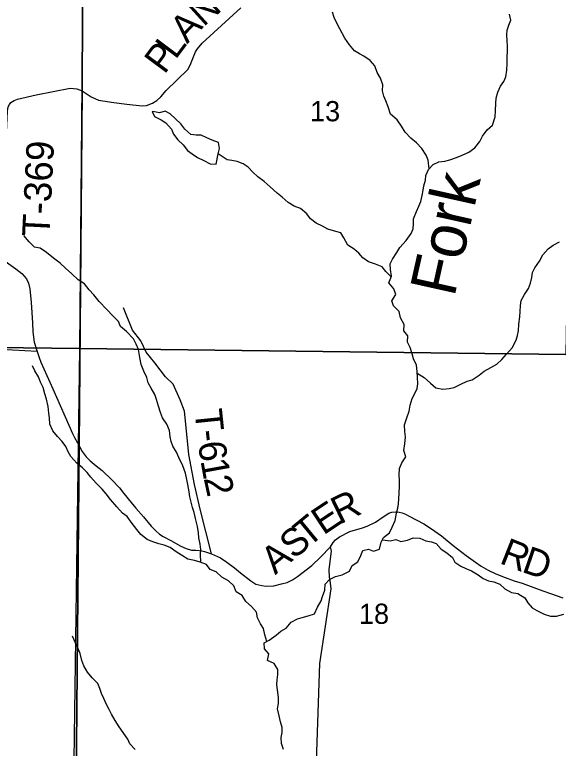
# Model space of a CAD drawing. Extents: x -3.6 to 34, y 0 to 32.8.
# Drawn here: x -2.947 to -1.822, y 28.286 to 29.806 of the extents above; entities that cross this region are included whole.
import ezdxf

# ---------------------------------------------------------------- set-up
doc = ezdxf.new("R2010")
doc.units = 0
for name, color, linetype in [('GM_X_Corporation', 7, 'Continuous'), ('GM_X_County_Road', 7, 'Continuous'), ('GM_X_County_Road_Text', 7, 'Continuous'), ('GM_X_Minor_Lake', 7, 'Continuous'), ('GM_X_Minor_River', 7, 'Continuous'), ('GM_X_Minor_River_Text', 7, 'Continuous'), ('GM_X_Section_Text', 7, 'Continuous'), ('GM_X_Township_Road', 7, 'Continuous'), ('GM_X_Township_Road_Text', 7, 'Continuous')]:
    doc.layers.add(name, color=color, linetype=linetype)

msp = doc.modelspace()

# ---------------------------------------------------------------- linework, layer by layer
at = {"layer": 'GM_X_Corporation'}
for points in [[(-3.6295, 30.6462), (-3.6295, 26.0429), (-2.8635, 26.0429), (-2.8499, 26.4099), (-2.8426, 27.1), (-2.8208, 28.0589), (-2.813, 28.9119), (-2.8073, 29.6484), (-2.8047, 30.129), (-2.8012, 30.524), (-2.8007, 30.6338), (-3.5736, 30.6453)], [(-3.6295, 30.1386), (-3.6295, 29.124), (-2.8121, 29.1143), (-2.8032, 30.1329)], [(-1.7886, 30.1145), (-1.8059, 29.1018), (-2.8121, 29.1143), (-2.8032, 30.1329)], [(-3.6295, 29.124), (-3.6295, 28.0641), (-2.8264, 28.0607), (-2.8121, 29.1143)], [(-2.8121, 29.1143), (-1.8059, 29.1018), (-1.7854, 29.1006), (-1.8056, 28.0368), (-2.8264, 28.0607)]]:
    msp.add_lwpolyline(points, close=True, dxfattribs=at)
msp.add_lwpolyline([(-0.398, 30.5946), (-0.453, 30.5952), (-0.5034, 30.5954), (-2.3541, 30.6318), (-2.7027, 30.634), (-2.8007, 30.6338), (-2.8012, 30.524), (-2.8047, 30.129), (-2.8073, 29.6484), (-2.813, 28.9119), (-2.8208, 28.0589), (-2.8426, 27.1), (-2.8499, 26.4099), (-2.8635, 26.0429), (2.3706, 26.0429)], dxfattribs=at)
at = {"layer": 'GM_X_County_Road'}
for points in [[(-2.976, 29.3021), (-2.9446, 29.2795), (-2.9318, 29.2695), (-2.922, 29.2586), (-2.9182, 29.2497), (-2.9154, 29.2377), (-2.9127, 29.2098), (-2.91, 29.1674), (-2.9089, 29.1491), (-2.9061, 29.1277), (-2.9005, 29.1079), (-2.8964, 29.0957), (-2.8926, 29.0857), (-2.8677, 29.0305), (-2.8274, 28.9384), (-2.8228, 28.9298), (-2.8167, 28.9188), (-2.8162, 28.9179)], [(-2.8162, 28.9179), (-2.8128, 28.9113), (-2.8074, 28.9009), (-2.7989, 28.89), (-2.7904, 28.8818), (-2.7778, 28.8715), (-2.7654, 28.8617), (-2.7449, 28.8417), (-2.7301, 28.8256), (-2.7206, 28.814), (-2.7055, 28.7956), (-2.696, 28.7836), (-2.6803, 28.7656), (-2.6642, 28.7461), (-2.6545, 28.7369), (-2.6468, 28.7296), (-2.6392, 28.7252), (-2.6239, 28.7165), (-2.6032, 28.7052), (-2.5915, 28.7), (-2.5806, 28.6969), (-2.5721, 28.6964), (-2.5652, 28.6961), (-2.5593, 28.6953), (-2.5542, 28.6938), (-2.5391, 28.6891), (-2.5209, 28.6811), (-2.508, 28.6715), (-2.4916, 28.6604), (-2.4797, 28.65), (-2.458, 28.6332), (-2.4476, 28.6265), (-2.4351, 28.6232), (-2.4266, 28.622), (-2.4107, 28.6231), (-2.3948, 28.6267), (-2.3827, 28.6299), (-2.3716, 28.6353), (-2.3617, 28.6424), (-2.332, 28.665), (-2.314, 28.682), (-2.293, 28.7034), (-2.2875, 28.7126), (-2.283, 28.7182), (-2.2744, 28.7246), (-2.2533, 28.7352), (-2.2268, 28.7428), (-2.217, 28.7465), (-2.2003, 28.7547), (-2.1841, 28.7655), (-2.1721, 28.7731), (-2.1662, 28.7752), (-2.1596, 28.776), (-2.1511, 28.7756), (-2.1448, 28.7737), (-2.138, 28.7709), (-2.1304, 28.7672), (-2.1, 28.7513), (-2.0843, 28.7409), (-2.0636, 28.7264), (-2.0393, 28.7061), (-2.012, 28.6856), (-1.9932, 28.6719), (-1.981, 28.6637), (-1.9666, 28.655), (-1.9507, 28.6473), (-1.9316, 28.64), (-1.9127, 28.6333), (-1.8963, 28.6281), (-1.8538, 28.6122), (-1.8378, 28.6067), (-1.8123, 28.5976)]]:
    msp.add_lwpolyline(points, dxfattribs=at)
at = {"layer": 'GM_X_Minor_Lake'}
for points in [[(-2.6576, 29.6045), (-2.6625, 29.6055), (-2.6574, 29.595), (-2.6437, 29.588), (-2.6337, 29.5817), (-2.6225, 29.5687), (-2.6182, 29.5585), (-2.6092, 29.5462), (-2.5981, 29.5361), (-2.5888, 29.5241), (-2.5792, 29.5175), (-2.5681, 29.5101), (-2.5551, 29.5035), (-2.5425, 29.4969), (-2.5296, 29.496), (-2.5259, 29.5173)], [(-2.5259, 29.5173), (-2.523, 29.5283), (-2.5247, 29.5412), (-2.5377, 29.5455), (-2.5491, 29.5506), (-2.5606, 29.5561), (-2.5708, 29.5563), (-2.5822, 29.5576), (-2.5949, 29.5688), (-2.603, 29.5796), (-2.6138, 29.59), (-2.625, 29.6005), (-2.6356, 29.606), (-2.6473, 29.6024), (-2.6576, 29.6045)]]:
    msp.add_lwpolyline(points, dxfattribs=at)
at = {"layer": 'GM_X_Minor_River'}
for points in [[(-2.0887, 29.4867), (-2.0911, 29.5042), (-2.0954, 29.5148), (-2.104, 29.5283), (-2.1148, 29.5406), (-2.1267, 29.5502), (-2.1386, 29.5625), (-2.1464, 29.5749), (-2.1554, 29.588), (-2.1688, 29.5999), (-2.1736, 29.6146), (-2.1787, 29.6274), (-2.1827, 29.6372), (-2.1855, 29.6478), (-2.185, 29.6607), (-2.1894, 29.6742), (-2.1968, 29.6859), (-2.2016, 29.6998), (-2.2112, 29.7106), (-2.2239, 29.7195), (-2.2334, 29.7247), (-2.2434, 29.7309), (-2.2538, 29.7429), (-2.2631, 29.7571), (-2.2741, 29.7767), (-2.2799, 29.7883), (-2.2854, 29.7996), (-2.2887, 29.8109)], [(-2.2306, 28.6857), (-2.2263, 28.6957), (-2.2146, 28.6985), (-2.2043, 28.6945), (-2.1915, 28.6989), (-2.1883, 28.7134), (-2.1832, 28.7229), (-2.1713, 28.7326), (-2.1654, 28.7441), (-2.1596, 28.7578), (-2.1564, 28.7731), (-2.154, 28.7833), (-2.1526, 28.7928), (-2.152, 28.8031), (-2.1507, 28.8149), (-2.1502, 28.8289), (-2.1504, 28.841), (-2.151, 28.8524), (-2.1505, 28.8657), (-2.1454, 28.8775), (-2.1373, 28.8901), (-2.1416, 28.903), (-2.1396, 28.9166), (-2.138, 28.9311), (-2.1393, 28.9424), (-2.1399, 28.9561), (-2.1349, 28.9705), (-2.1306, 28.9843), (-2.1285, 28.9972), (-2.1238, 29.0105), (-2.1183, 29.0212), (-2.1136, 29.0316), (-2.1122, 29.0414), (-2.1132, 29.0551), (-2.1134, 29.0668), (-2.1148, 29.0797), (-2.1215, 29.0932), (-2.1239, 29.1034), (-2.1283, 29.1166), (-2.1334, 29.1275), (-2.1333, 29.1408), (-2.141, 29.1509), (-2.1405, 29.1641), (-2.1483, 29.178), (-2.1512, 29.1912), (-2.1627, 29.2028), (-2.1663, 29.213), (-2.1578, 29.226), (-2.1622, 29.2381), (-2.1726, 29.2504), (-2.1672, 29.2641), (-2.1689, 29.2777), (-2.1695, 29.2899), (-2.1651, 29.2994), (-2.1555, 29.3128), (-2.1493, 29.3236), (-2.1366, 29.3378), (-2.1259, 29.3528), (-2.1219, 29.3623), (-2.1214, 29.3726), (-2.1215, 29.3832), (-2.1154, 29.3984), (-2.1102, 29.4091), (-2.1059, 29.4187), (-2.1034, 29.4309), (-2.101, 29.4419), (-2.0996, 29.4514), (-2.0968, 29.4628), (-2.0958, 29.4727), (-2.09, 29.4853), (-2.0807, 29.4953), (-2.0687, 29.5008), (-2.0566, 29.5025), (-2.0464, 29.5054), (-2.0325, 29.5098), (-2.0208, 29.5145), (-2.0069, 29.5208), (-1.9942, 29.5301), (-1.9842, 29.5428), (-1.9787, 29.5539), (-1.9691, 29.567), (-1.9576, 29.5766), (-1.9526, 29.5941), (-1.9516, 29.6063), (-1.9512, 29.6222), (-1.9502, 29.6325), (-1.947, 29.6454), (-1.9415, 29.6576), (-1.9345, 29.6672), (-1.9301, 29.6768), (-1.9281, 29.6908), (-1.9272, 29.7045), (-1.9274, 29.7174), (-1.9269, 29.731), (-1.9271, 29.7409), (-1.9276, 29.7507), (-1.9279, 29.764), (-1.9276, 29.7735), (-1.924, 29.7842), (-1.9201, 29.7941), (-1.9225, 29.8069)], [(-2.1677, 29.2628), (-2.1787, 29.2738), (-2.1861, 29.2835), (-2.1998, 29.2893), (-2.2142, 29.2936), (-2.2261, 29.3018), (-2.2342, 29.3115), (-2.2442, 29.32), (-2.2572, 29.3282), (-2.2654, 29.3432), (-2.2717, 29.3537), (-2.282, 29.3565), (-2.2983, 29.3612), (-2.3098, 29.3674), (-2.3231, 29.374), (-2.3346, 29.3829), (-2.3424, 29.3934), (-2.3551, 29.4046), (-2.3684, 29.4089), (-2.3806, 29.4166), (-2.3933, 29.4274), (-2.4033, 29.4363), (-2.4183, 29.449), (-2.4306, 29.4605), (-2.4433, 29.4702), (-2.454, 29.4794), (-2.4637, 29.4899), (-2.4736, 29.4965), (-2.4862, 29.5016), (-2.4976, 29.5037), (-2.5071, 29.5054), (-2.5259, 29.5173)], [(-2.5618, 28.6714), (-2.5619, 28.6884), (-2.5617, 28.6979), (-2.5627, 28.7093), (-2.5655, 28.7221), (-2.5665, 28.7323), (-2.5686, 28.7459), (-2.5726, 28.7622), (-2.5751, 28.7746), (-2.5787, 28.7852), (-2.5812, 28.7961), (-2.584, 28.8074), (-2.5857, 28.8176), (-2.5882, 28.8328), (-2.5907, 28.8433), (-2.5932, 28.8562), (-2.5984, 28.8716), (-2.607, 28.8889), (-2.6117, 28.8995), (-2.6195, 28.9118), (-2.6227, 28.9216), (-2.6248, 28.9315), (-2.6265, 28.9443), (-2.632, 28.9575), (-2.6406, 28.9706), (-2.6453, 28.9815), (-2.649, 28.9951), (-2.6534, 29.0087), (-2.6569, 29.0188), (-2.6644, 29.0324), (-2.6702, 29.0433), (-2.6734, 29.0542), (-2.6794, 29.0674), (-2.6853, 29.0809), (-2.6874, 29.096), (-2.6903, 29.1123), (-2.6951, 29.1232), (-2.7009, 29.1341), (-2.7152, 29.1494), (-2.7275, 29.1598), (-2.7318, 29.1699), (-2.7434, 29.1819), (-2.7558, 29.1953), (-2.7716, 29.2117), (-2.7828, 29.2252), (-2.7924, 29.236), (-2.8025, 29.248), (-2.8151, 29.2568), (-2.8282, 29.2691), (-2.8416, 29.281), (-2.8528, 29.2911), (-2.8662, 29.3015), (-2.8812, 29.313), (-2.8942, 29.3218), (-2.906, 29.3239), (-2.9168, 29.3351), (-2.928, 29.3485)], [(-2.1134, 29.063), (-2.0992, 29.0542), (-2.0861, 29.0423), (-2.075, 29.0326), (-2.0606, 29.0298), (-2.0473, 29.0312), (-2.0372, 29.0336), (-2.0233, 29.0403), (-2.0101, 29.0466), (-1.9996, 29.0494), (-1.9854, 29.0591), (-1.9749, 29.0677), (-1.9614, 29.0747), (-1.949, 29.0818), (-1.9382, 29.0914), (-1.9286, 29.1026), (-1.9171, 29.116), (-1.909, 29.1313), (-1.9058, 29.1409), (-1.9037, 29.1508), (-1.9035, 29.1648), (-1.9015, 29.1796), (-1.9006, 29.191), (-1.9, 29.2031), (-1.8987, 29.2134), (-1.8913, 29.226), (-1.8836, 29.2387), (-1.8789, 29.2497), (-1.8764, 29.2611), (-1.8747, 29.2714), (-1.8703, 29.2817), (-1.8607, 29.2951), (-1.8534, 29.3085), (-1.8426, 29.3205), (-1.8322, 29.3286), (-1.8194, 29.3353)], [(-2.4247, 28.5077), (-2.4292, 28.5212), (-2.4321, 28.5341), (-2.4379, 28.5442), (-2.4442, 28.5566), (-2.4463, 28.568), (-2.4567, 28.5803), (-2.4686, 28.5903), (-2.4757, 28.6027), (-2.4883, 28.6105), (-2.493, 28.6225), (-2.5042, 28.6333), (-2.5179, 28.6406), (-2.5295, 28.6518), (-2.5421, 28.6565), (-2.5498, 28.667), (-2.5628, 28.6717), (-2.5746, 28.6753), (-2.5886, 28.6781), (-2.6016, 28.6866), (-2.6123, 28.6932), (-2.625, 28.7021), (-2.6372, 28.7068), (-2.6486, 28.7101), (-2.6608, 28.714), (-2.6726, 28.7187), (-2.6856, 28.7291), (-2.6938, 28.7392), (-2.7035, 28.752), (-2.7139, 28.7662), (-2.7235, 28.7736), (-2.7351, 28.7863), (-2.7486, 28.8016), (-2.7571, 28.8132), (-2.766, 28.8229), (-2.7783, 28.8356), (-2.7895, 28.8479), (-2.7965, 28.8576), (-2.8061, 28.867), (-2.8184, 28.877), (-2.8304, 28.8908), (-2.8359, 28.9006), (-2.841, 28.9111), (-2.8483, 28.9216), (-2.858, 28.9324), (-2.8676, 28.944), (-2.8739, 28.9579), (-2.8745, 28.9704), (-2.8758, 28.9802), (-2.8772, 28.9939), (-2.8809, 29.0093), (-2.8845, 29.0203), (-2.8877, 29.0335), (-2.8932, 29.0448), (-2.8976, 29.0553), (-2.9054, 29.0681), (-2.9097, 29.0782)], [(-2.1857, 28.7183), (-2.1695, 28.716), (-2.1578, 28.7185), (-2.1475, 28.7148), (-2.1339, 28.7173), (-2.1219, 28.7221), (-2.1082, 28.7212), (-2.0956, 28.7157), (-2.0843, 28.7136), (-2.0747, 28.7108), (-2.0643, 28.6988), (-2.0521, 28.6911), (-2.0409, 28.6818), (-2.0358, 28.6716), (-2.0236, 28.6635), (-2.0133, 28.6588), (-2.0011, 28.654), (-1.9873, 28.6459), (-1.977, 28.6382), (-1.9659, 28.633), (-1.9553, 28.6309), (-1.9427, 28.6262), (-1.9323, 28.6166), (-1.9182, 28.6088), (-1.9053, 28.6068), (-1.8911, 28.5976), (-1.8849, 28.5878), (-1.876, 28.577), (-1.8664, 28.5714), (-1.8512, 28.5641), (-1.8378, 28.5598), (-1.8253, 28.56), (-1.8099, 28.5641)], [(-2.3907, 28.2838), (-2.3943, 28.2963), (-2.3949, 28.3088), (-2.3932, 28.3187), (-2.3934, 28.3297), (-2.3966, 28.341), (-2.3995, 28.3534), (-2.4027, 28.3682), (-2.4006, 28.3792), (-2.4009, 28.3917), (-2.403, 28.4072), (-2.404, 28.4178), (-2.4034, 28.4284), (-2.4021, 28.4391), (-2.4022, 28.4493), (-2.41, 28.4617), (-2.4234, 28.4679), (-2.4206, 28.482), (-2.4298, 28.4924), (-2.4301, 28.5049), (-2.4203, 28.51), (-2.4057, 28.5205), (-2.3956, 28.529), (-2.3848, 28.5353), (-2.3744, 28.5476), (-2.3613, 28.5542), (-2.3515, 28.5571), (-2.3394, 28.5607), (-2.3259, 28.5647), (-2.32, 28.5788), (-2.3123, 28.5915), (-2.3098, 28.601), (-2.3051, 28.614), (-2.3042, 28.6261), (-2.2949, 28.6357), (-2.2825, 28.642), (-2.2689, 28.6453), (-2.2536, 28.6531), (-2.2481, 28.665), (-2.2365, 28.6728), (-2.2306, 28.6857)], [(-2.6973, 28.2835), (-2.7081, 28.2955), (-2.7128, 28.3052), (-2.7307, 28.3311), (-2.7385, 28.3442), (-2.7463, 28.357), (-2.751, 28.3667), (-2.7564, 28.3769), (-2.762, 28.3893), (-2.7671, 28.3995), (-2.7703, 28.4104), (-2.775, 28.4206), (-2.7862, 28.4325), (-2.7958, 28.4441), (-2.8036, 28.4568), (-2.8076, 28.4678), (-2.8113, 28.4825), (-2.8152, 28.4923), (-2.8219, 28.5058), (-2.827, 28.5186)]]:
    msp.add_lwpolyline(points, dxfattribs=at)
at = {"layer": 'GM_X_Township_Road'}
for points in [[(-2.8127, 29.6499), (-2.8071, 29.6478), (-2.7887, 29.6355), (-2.7735, 29.6287), (-2.7416, 29.6236), (-2.7148, 29.6203), (-2.6827, 29.6171), (-2.6738, 29.6174), (-2.6618, 29.6227), (-2.6525, 29.6281), (-2.644, 29.6356), (-2.6329, 29.6489), (-2.5887, 29.6921), (-2.5835, 29.7014), (-2.5727, 29.7286), (-2.5683, 29.7352), (-2.5588, 29.7467), (-2.4785, 29.8197)], [(-2.976, 29.3021), (-2.9613, 29.6061), (-2.9604, 29.615), (-2.9576, 29.6199), (-2.9545, 29.6241), (-2.9475, 29.6281), (-2.9412, 29.6307), (-2.9024, 29.6397), (-2.8319, 29.6537), (-2.8184, 29.6519), (-2.8127, 29.6499)], [(-2.5391, 28.6891), (-2.5626, 28.7818), (-2.5748, 28.8328), (-2.586, 28.8948), (-2.5912, 28.944), (-2.5953, 28.9844), (-2.6041, 29.0078), (-2.6187, 29.0406), (-2.6347, 29.0559), (-2.6565, 29.0845), (-2.6746, 29.1064), (-2.6856, 29.1303), (-2.7026, 29.1522), (-2.7214, 29.1985)], [(-2.9005, 29.1079), (-2.951, 29.1106), (-3.0499, 29.1125), (-3.0568, 29.1112), (-3.059, 29.1081), (-3.0606, 29.1009), (-3.0714, 28.4922)], [(-2.3279, 28.0951), (-2.3155, 28.462), (-2.2916, 28.6164), (-2.293, 28.6284), (-2.295, 28.6415), (-2.296, 28.6558), (-2.2937, 28.6731), (-2.2913, 28.6946), (-2.293, 28.7034)]]:
    msp.add_lwpolyline(points, dxfattribs=at)

# ---------------------------------------------------------------- texts
at = {"layer": 'GM_X_County_Road_Text'}
for s, rotation, p in [('R', 25.8022, (-2.2743, 28.7493)), ('E', 33.5355, (-2.3079, 28.7268)), ('T', 39.4549, (-2.3395, 28.7008)), ('S', 39.544, (-2.369, 28.6764)), ('R', 338.4947, (-1.9455, 28.6704)), ('A', 39.5476, (-2.4076, 28.6445)), ('D', 341.0248, (-1.8995, 28.6523))]:
    msp.add_text(s, height=0.0568, rotation=rotation, dxfattribs=at).set_placement(p)
at = {"layer": 'GM_X_Minor_River_Text'}
msp.add_text('Fork', height=0.09468, rotation=77.4351, dxfattribs=at).set_placement((-2.0369, 29.2188))
at = {"layer": 'GM_X_Section_Text'}
for s, p in [('13', (-2.3354, 29.5849)), ('18', (-2.2342, 28.544))]:
    msp.add_text(s, height=0.04186, rotation=0, dxfattribs=at).set_placement(p)
at = {"layer": 'GM_X_Township_Road_Text'}
for s, height, rotation, p in [('N', 0.0568, 42.226, (-2.556, 29.7792)), ('A', 0.0568, 46.2429, (-2.5898, 29.7439)), ('L', 0.0568, 53.1751, (-2.6141, 29.7112)), ('P', 0.0568, 53.3501, (-2.6369, 29.6805)), ('T-369', 0.05682, 87.1941, (-2.8748, 29.345)), ('T', 0.0568, 275.8471, (-2.5746, 28.9864)), ('-', 0.0568, 276.0815, (-2.5702, 28.944)), ('6', 0.0568, 277.8801, (-2.5675, 28.9191)), ('1', 0.0568, 280.2318, (-2.5624, 28.8822)), ('2', 0.0568, 282.3599, (-2.5558, 28.8457))]:
    msp.add_text(s, height=height, rotation=rotation, dxfattribs=at).set_placement(p)

doc.saveas('drawing.dxf')
